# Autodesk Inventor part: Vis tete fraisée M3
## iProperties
Author: Flavien MARTY
Shininess: 100.0
PropertySet Name: _Private Model Information
Created: 2001-10
Part Number: Vis tete fraisée M3
Material: Par défaut
Document SubType Name: Modélisation
Designer: Flavien MARTY
Control State: 0
Master: False
Checked Out: False
PropertySet Name: Design Tracking Control
Density: 0.0
Volumn: 0.0
Area: 0.0
PropertySet Name: Model Information
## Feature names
1. Base1
